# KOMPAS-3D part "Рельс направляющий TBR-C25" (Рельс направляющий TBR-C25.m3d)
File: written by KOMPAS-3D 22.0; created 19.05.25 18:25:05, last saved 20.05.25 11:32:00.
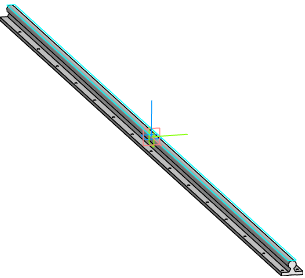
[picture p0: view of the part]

Document properties: Автор: user; Полное имя файла: D:\Рабочая папка\АРХИВ\612\05\Задание №6 - Тележка для крыши\3Д\Рельс направляющий TBR-C25.m3d

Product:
- Part/product: Рельс направляющий TBR-C25
    Масса: 29.607689
    Раздел спецификации: Прочие изделия
    Примечание: L=3 м

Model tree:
1. Эскиз:1
2. Элемент выдавливания:1
     Расстояние 1 = 3000
3. Эскиз:2  (with: Элемент выдавливания:1)
4. Элемент выдавливания:2  (with: Элемент выдавливания:1)
     Расстояние 2 = 3000
5. Фаска:1  (with: Элемент выдавливания:2)
     Угол = 45; Длина 1 = 1; Длина 2 = 1
6. Эскиз:3  (with: Элемент выдавливания:2)
7. Элемент выдавливания:3
     Расстояние 2 = 10
8. Касательная плоскость:1  (with: Элемент выдавливания:1)
     Угол = -90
